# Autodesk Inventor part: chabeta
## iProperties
Shininess: 64.0
Length Units: 11272
Angle Units: 11279
Time Units: 11290
Mass Units: 11286
Length Display Precision: 3
Angle Display Precision: 2
Compacted: True
Part Number: chabeta
Document SubType Name: Modeling
Created: 2005-06
Designer: Alek
Manufacturer: Standard
Standards Organization: Custom
Density: 0.0
Volumn: 0.0
Area: 0.0
PropertySet Name: Model Information
Control State: 0
Master: False
Checked Out: False
Author: Alek
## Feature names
1. Extrusion2
